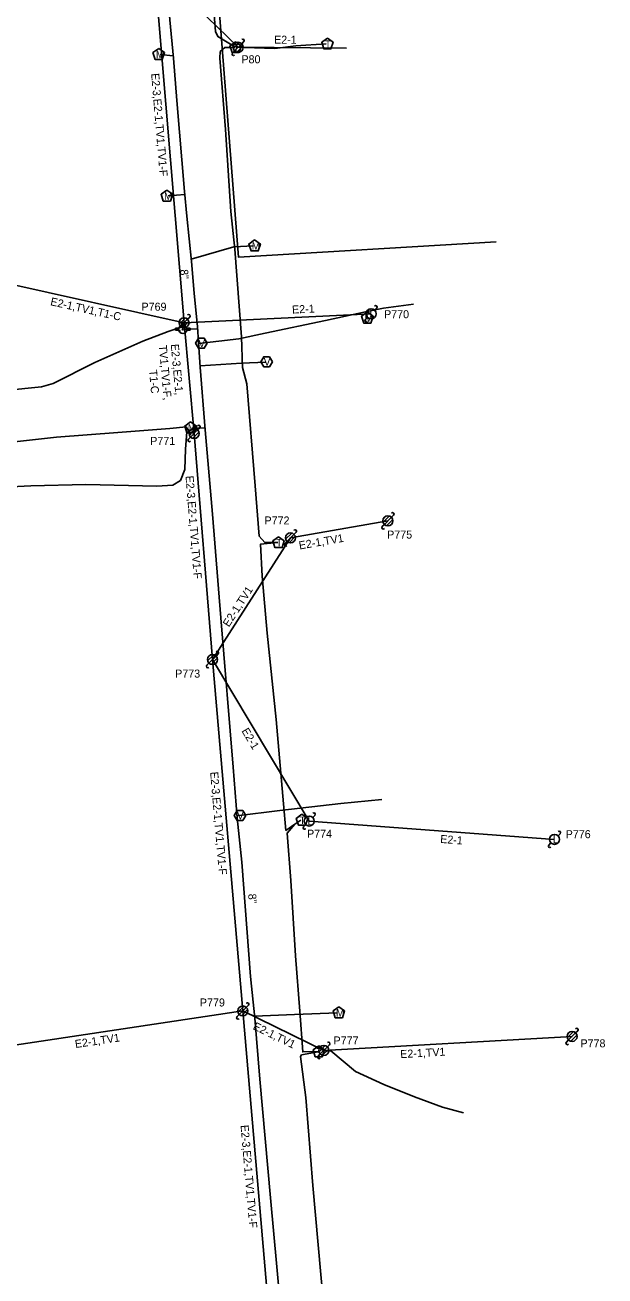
# Model space of a CAD drawing. Extents: x 1614474 to 1865144, y 1098877 to 1212550.
# Drawn here: x 1756233 to 1756523, y 1167576 to 1168201 of the extents above; entities that cross this region are included whole.
import ezdxf

# ---------------------------------------------------------------- set-up
doc = ezdxf.new("R2010")
doc.units = 0
for name, color, linetype in [('RD_EX_SU_Elec', 7, 'Continuous'), ('RD_EX_SU_H2O', 7, 'Continuous'), ('RD_EX_SU_Ovhd', 7, 'Continuous'), ('RD_EX_SU_Pole', 7, 'Continuous'), ('RD_EX_SU_Sewer', 7, 'Continuous'), ('RD_EX_SU_Telecom', 7, 'Continuous'), ('RD_EX_SU_TX_H2O', 7, 'Continuous'), ('RD_EX_SU_TX_Pole', 7, 'Continuous')]:
    doc.layers.add(name, color=color, linetype=linetype)

# ---------------------------------------------------------------- blocks, each defined once
blk = doc.blocks.new('SUE_WM')
at = {"layer": 'RD_EX_SU_H2O'}
blk.add_lwpolyline([(0, 3.05), (-2.9, 0.94), (-1.79, -2.47), (1.79, -2.47), (2.9, 0.94)], close=True, dxfattribs=at)
blk.add_text('M', height=3.75, dxfattribs=at).set_placement((-1.43, -1.88))
blk = doc.blocks.new('SUE_TPP')
at = {"layer": 'RD_EX_SU_Telecom'}
blk.add_lwpolyline([(0, 3), (-2.85, 0.93), (-1.76, -2.43), (1.76, -2.43), (2.85, 0.93)], close=True, dxfattribs=at)
blk.add_text('T', height=3.75, dxfattribs=at).set_placement((-1.25, -1.88))
blk = doc.blocks.new('SUE_WFH')
at = {"layer": 'RD_EX_SU_H2O'}
for p, q in [((-2.01, 0.6), (-3.65, 0.6)), ((-3.65, 0.6), (-3.65, -0.45)), ((-0.48, 3.38), (-0.48, 2.04)), ((0.57, 3.38), (-0.48, 3.38)), ((0.57, 2.02), (0.57, 3.38)), ((3.7, 0.6), (2.01, 0.6)), ((3.7, -0.45), (3.7, 0.6)), ((-3.65, -0.45), (-2.05, -0.45)), ((2.05, -0.45), (3.7, -0.45))]:
    blk.add_line(p, q, dxfattribs=at)
for radius in [2.1, 0.263]:
    blk.add_circle((0, 0), radius, dxfattribs=at)
for start, end in [(163.3387, 192.31502), (74.24552, 103.21276), (347.68498, 16.6613)]:
    blk.add_arc((0, 0), 2.1, start, end, dxfattribs=at)
blk = doc.blocks.new('SUE_WV')
at = {"layer": 'RD_EX_SU_H2O'}
blk.add_lwpolyline([(2.89, 0), (1.44, 2.5), (-1.44, 2.5), (-2.89, 0), (-1.44, -2.5), (1.44, -2.5)], close=True, dxfattribs=at)
blk.add_text('V', height=3.75, dxfattribs=at).set_placement((-1.43, -1.88))
blk = doc.blocks.new('SUE_PP')
at = {"layer": 'RD_EX_SU_Pole'}
for p, q in [((-2.41, -0.65), (0.65, 2.41)), ((-1.77, -1.77), (1.77, 1.77)), ((-0.65, -2.41), (2.41, 0.65)), ((1.77, 1.77), (2.83, 2.83)), ((-2.83, -2.83), (-1.77, -1.77))]:
    blk.add_line(p, q, dxfattribs=at)
blk.add_circle((0, 0), 2.5, dxfattribs=at)
for centre, start, end in [((2.3, 3.36), 315, 135), ((-2.3, -3.36), 135, 315)]:
    blk.add_arc(centre, 0.75, start, end, dxfattribs=at)

msp = doc.modelspace()

# ---------------------------------------------------------------- linework, layer by layer
at = {"layer": 'RD_EX_SU_Elec'}
msp.add_lwpolyline([(1756158.7, 1167983.99), (1756163.59, 1167983.56), (1756187.17, 1167988.03), (1756217.4, 1167991.66), (1756249.02, 1167995.12), (1756279.77, 1167997.42), (1756305.79, 1167999.38), (1756313.88, 1168000.27), (1756316.19, 1167996.26)], dxfattribs=at)
at = {"layer": 'RD_EX_SU_H2O'}
for p, q in [((1756307.47, 1168185.66), (1756300.96, 1168186.31)), ((1756313.25, 1168116.46), (1756304.98, 1168115.68)), ((1756404.41, 1168055.03), (1756404.06, 1168057.9)), ((1756319.41, 1168049.21), (1756313.16, 1168048.96)), ((1756323.32, 1167999.75), (1756316.73, 1167999.65))]:
    msp.add_line(p, q, dxfattribs=at)
for points in [[(1756285.17, 1168453.36), (1756286.98, 1168430.89), (1756288.84, 1168410.54), (1756290.69, 1168387.38), (1756292.59, 1168362.89), (1756293.61, 1168347.16), (1756296.92, 1168313.47), (1756298.02, 1168299), (1756300.93, 1168264.73), (1756302.72, 1168240.2), (1756304.28, 1168222.7), (1756305.65, 1168203.75), (1756307.59, 1168184.55), (1756309.19, 1168163.34), (1756313.11, 1168117.87), (1756314.27, 1168105.58), (1756316.49, 1168082.9), (1756317.85, 1168067.08)], [(1756316.37, 1168084.09), (1756337.79, 1168090.19), (1756347.49, 1168090.77)], [(1756317.85, 1168067.08), (1756319.54, 1168050.19), (1756320.11, 1168042.67), (1756320.97, 1168030.07), (1756323.39, 1167998.84), (1756327.05, 1167956.56), (1756331.25, 1167904.83), (1756337.4, 1167830.13), (1756339.37, 1167804.89), (1756341.64, 1167782.73), (1756346.05, 1167725.54), (1756348.16, 1167704.76), (1756350.69, 1167674.25), (1756356.07, 1167614.92), (1756363.99, 1167527.76)], [(1756320.16, 1168041.86), (1756340.19, 1168044.22), (1756353.43, 1168047.04), (1756383.46, 1168053.37), (1756403.52, 1168057.78), (1756412.53, 1168059.65), (1756427.58, 1168061.53)], [(1756320.92, 1168030.83), (1756341.5, 1168032.11), (1756353.7, 1168032.64)], [(1756339.29, 1167805.94), (1756360.77, 1167808.6), (1756391.2, 1167811.99), (1756411.72, 1167814.03)], [(1756348.06, 1167705.73), (1756368.09, 1167706.65), (1756389.58, 1167707.36)]]:
    msp.add_lwpolyline(points, dxfattribs=at)
at = {"layer": 'RD_EX_SU_Ovhd'}
for p, q in [((1756297.87, 1168230.98), (1756339.88, 1168189.94)), ((1756297.87, 1168230.98), (1756312.84, 1168052.28)), ((1756339.88, 1168189.94), (1756394.05, 1168189.45)), ((1756221.7, 1168072.64), (1756312.84, 1168052.28)), ((1756312.84, 1168052.28), (1756406.3, 1168056.76)), ((1756312.84, 1168052.28), (1756317.86, 1167996.94)), ((1756317.86, 1167996.94), (1756327.05, 1167883.97)), ((1756366, 1167944.76), (1756414.72, 1167953.29)), ((1756327.05, 1167883.97), (1756366, 1167944.76)), ((1756327.05, 1167883.97), (1756342.18, 1167708.36)), ((1756327.05, 1167883.97), (1756375.39, 1167803.26)), ((1756375.39, 1167803.26), (1756497.97, 1167794.1)), ((1756206.43, 1167688.08), (1756342.18, 1167708.36)), ((1756342.18, 1167708.36), (1756356.4, 1167543.03)), ((1756342.18, 1167708.36), (1756382.71, 1167688.62)), ((1756382.71, 1167688.62), (1756506.75, 1167695.61))]:
    msp.add_line(p, q, dxfattribs=at)
at = {"layer": 'RD_EX_SU_Pole'}
for p, q in [((1756337.05, 1168187.11), (1756338.11, 1168188.17)), ((1756337.46, 1168189.29), (1756340.52, 1168192.35)), ((1756338.11, 1168188.17), (1756341.64, 1168191.71)), ((1756339.23, 1168187.53), (1756342.29, 1168190.59)), ((1756341.64, 1168191.71), (1756342.7, 1168192.77)), ((1756408.06, 1168058.53), (1756409.12, 1168059.59)), ((1756403.47, 1168053.93), (1756404.53, 1168054.99)), ((1756411.89, 1167950.46), (1756412.95, 1167951.52)), ((1756412.3, 1167952.64), (1756415.36, 1167955.71)), ((1756412.95, 1167951.52), (1756416.48, 1167955.06)), ((1756414.07, 1167950.88), (1756417.13, 1167953.94)), ((1756416.48, 1167955.06), (1756417.54, 1167956.12)), ((1756363.59, 1167944.11), (1756366.65, 1167947.17)), ((1756364.24, 1167942.99), (1756367.77, 1167946.52)), ((1756365.36, 1167942.34), (1756368.42, 1167945.4)), ((1756367.77, 1167946.52), (1756368.83, 1167947.59)), ((1756363.17, 1167941.93), (1756364.24, 1167942.99)), ((1756324.22, 1167881.14), (1756325.28, 1167882.2)), ((1756324.63, 1167883.32), (1756327.69, 1167886.38)), ((1756325.28, 1167882.2), (1756328.81, 1167885.74)), ((1756326.4, 1167881.56), (1756329.46, 1167884.62)), ((1756328.81, 1167885.74), (1756329.87, 1167886.8)), ((1756372.56, 1167800.43), (1756373.62, 1167801.5)), ((1756377.16, 1167805.03), (1756378.22, 1167806.09)), ((1756499.74, 1167795.87), (1756500.8, 1167796.93)), ((1756495.14, 1167791.27), (1756496.21, 1167792.33))]:
    msp.add_line(p, q, dxfattribs=at)
for centre in [(1756339.88, 1168189.94), (1756406.3, 1168056.76), (1756414.72, 1167953.29), (1756366, 1167944.76), (1756327.05, 1167883.97), (1756375.39, 1167803.26), (1756497.97, 1167794.1)]:
    msp.add_circle(centre, 2.5, dxfattribs=at)
for centre, start, end in [((1756342.17, 1168193.3), 315, 135), ((1756337.58, 1168186.58), 135, 315), ((1756408.59, 1168060.12), 315, 135), ((1756404, 1168053.4), 135, 315), ((1756417.01, 1167956.65), 315, 135), ((1756368.3, 1167948.12), 315, 135), ((1756412.42, 1167949.93), 135, 315), ((1756363.71, 1167941.4), 135, 315), ((1756329.34, 1167887.33), 315, 135), ((1756324.75, 1167880.61), 135, 315), ((1756377.69, 1167806.62), 315, 135), ((1756373.09, 1167799.9), 135, 315), ((1756500.27, 1167797.46), 315, 135), ((1756495.67, 1167790.74), 135, 315)]:
    msp.add_arc(centre, 0.75, start, end, dxfattribs=at)
at = {"layer": 'RD_EX_SU_Sewer'}
msp.add_lwpolyline([(1756311.13, 1168456.78), (1756340.11, 1168085.05), (1756468.76, 1168092.7)], dxfattribs=at)
at = {"layer": 'RD_EX_SU_Telecom'}
for points in [[(1756308.42, 1168448.32), (1756311.91, 1168423.81), (1756311.76, 1168420.79), (1756309.33, 1168416.48), (1756312.58, 1168380.89), (1756316.49, 1168351.19), (1756321.57, 1168300.36), (1756322.32, 1168273.16), (1756326.95, 1168219.13), (1756328.55, 1168197.8), (1756329.78, 1168195.34), (1756338.22, 1168190.16)], [(1756338.16, 1168189.78), (1756333.21, 1168189.81), (1756330.86, 1168187.79), (1756330.68, 1168184.52), (1756333.54, 1168148.9), (1756336.25, 1168107.92), (1756338.14, 1168089.1), (1756341.61, 1168045.19), (1756342.02, 1168029.89), (1756344.16, 1168021.72), (1756348.34, 1167970.86), (1756350.41, 1167945.66), (1756353.23, 1167942.43), (1756359.64, 1167942.51)], [(1756339.2, 1168190.05), (1756342.94, 1168189.85), (1756358.25, 1168189.37), (1756368.67, 1168190.63), (1756383.86, 1168191.61)], [(1756159.04, 1167984.63), (1756166.68, 1167984.37), (1756176.55, 1167987.23), (1756186.47, 1167992.4), (1756190.44, 1167996.92), (1756193.4, 1168006.42), (1756198.16, 1168010.87), (1756216.42, 1168016.99), (1756223.51, 1168018.39), (1756241.64, 1168020.25), (1756247.48, 1168021.99), (1756268.27, 1168032.44), (1756292.3, 1168043.12), (1756304.83, 1168047.91), (1756313.37, 1168050.78), (1756313.03, 1168052.57)], [(1756158.59, 1167985.22), (1756162.2, 1167983.17), (1756168.33, 1167976.76), (1756180.21, 1167969.34), (1756190.12, 1167968.53), (1756236.31, 1167970.8), (1756263.75, 1167971.46), (1756299.2, 1167970.68), (1756307.27, 1167971.19), (1756311.09, 1167973.51), (1756313.18, 1167978.88), (1756313.61, 1167989.06), (1756314.16, 1167997.74), (1756316.41, 1167997.29)], [(1756359.48, 1167942.44), (1756351.11, 1167941.7), (1756351.95, 1167925.63), (1756354.4, 1167897.16), (1756358.92, 1167853.95), (1756362.5, 1167811.93), (1756363.77, 1167798.56), (1756368.25, 1167801.76), (1756371.25, 1167803.66)], [(1756371.22, 1167803.69), (1756368.25, 1167801.64), (1756364.32, 1167797.23), (1756366.22, 1167773.48), (1756368.54, 1167735.91), (1756370.77, 1167708.23), (1756372.16, 1167687.85), (1756379.89, 1167688.13)], [(1756383.1, 1167688.32), (1756386.12, 1167688.46), (1756398.58, 1167678.13), (1756412.62, 1167671.56), (1756428, 1167665.46), (1756441.94, 1167660.34), (1756452.56, 1167657.36)], [(1756379.84, 1167687.97), (1756371.61, 1167686.43), (1756371.04, 1167685.63), (1756373.7, 1167665.14), (1756377.25, 1167621.18), (1756381.27, 1167576.66), (1756385.09, 1167535.47)]]:
    msp.add_lwpolyline(points, dxfattribs=at)

# ---------------------------------------------------------------- block references
at = {"layer": 'RD_EX_SU_H2O'}
for name, p in [('SUE_WM', (1756300.18, 1168186.37)), ('SUE_WM', (1756304.26, 1168115.55)), ('SUE_WM', (1756348.09, 1168090.67)), ('SUE_WM', (1756404.46, 1168054.62)), ('SUE_WFH', (1756312.24, 1168049.01)), ('SUE_WV', (1756321.45, 1168042.03)), ('SUE_WV', (1756354.1, 1168032.8)), ('SUE_WM', (1756316.09, 1167999.71)), ('SUE_WV', (1756340.74, 1167806.05)), ('SUE_WM', (1756390.2, 1167707.41))]:
    msp.add_blockref(name, p, dxfattribs=at)
at = {"layer": 'RD_EX_SU_Pole'}
for p in [(1756312.84, 1168052.28), (1756317.86, 1167996.94), (1756342.18, 1167708.36), (1756506.75, 1167695.61), (1756382.71, 1167688.62)]:
    msp.add_blockref('SUE_PP', p, dxfattribs=at)
at = {"layer": 'RD_EX_SU_Telecom'}
for p in [(1756384.5, 1168191.53), (1756338.61, 1168189.72), (1756360.03, 1167942.36), (1756371.77, 1167803.65), (1756380.17, 1167687.93)]:
    msp.add_blockref('SUE_TPP', p, dxfattribs=at)

# ---------------------------------------------------------------- texts
at = {"layer": 'RD_EX_SU_Ovhd'}
for s, rotation, p in [('E2-1', 359.47922, (1756357.8, 1168191.78)), ('E2-3,E2-1,TV1,TV1-F', 274.78694, (1756296.39, 1168176.83)), ('E2-1,TV1,T1-C', 347.40599, (1756245.77, 1168061.11)), ('E2-1', 2.7473, (1756366.89, 1168056.87)), ('TV1,TV1-F,', 275.18336, (1756300.22, 1168040.97)), ('E2-3,E2-1,', 275.18336, (1756306.2, 1168041.51)), ('T1-C', 275.18336, (1756295.32, 1168028.58)), ('E2-3,E2-1,TV1,TV1-F', 274.64996, (1756313.57, 1167975.68)), ('E2-1,TV1', 9.9369, (1756370.58, 1167938.96)), ('E2-1,TV1', 57.34496, (1756335.26, 1167899.93)), ('E2-1', 300.92124, (1756341.41, 1167848.31)), ('E2-3,E2-1,TV1,TV1-F', 274.92539, (1756325.87, 1167827.73)), ('E2-1', 355.72628, (1756440.74, 1167792.36)), ('E2-1,TV1', 334.02741, (1756346.93, 1167699.37)), ('E2-1,TV1', 8.49892, (1756258.61, 1167689.81)), ('E2-1,TV1', 3.22525, (1756420.98, 1167684.76)), ('E2-3,E2-1,TV1,TV1-F', 274.91654, (1756341.07, 1167651.24))]:
    msp.add_text(s, height=4, rotation=rotation, dxfattribs=at).set_placement(p)
at = {"layer": 'RD_EX_SU_Pole'}
for p in [(1756405.43, 1168054.76), (1756374.53, 1167801.26), (1756497.11, 1167792.1)]:
    msp.add_text('L', height=4, dxfattribs=at).set_placement(p)
at = {"layer": 'RD_EX_SU_TX_H2O'}
for rotation, p in [(274.92643, (1756310.82, 1168078.81)), (274.41179, (1756344.87, 1167766.81))]:
    msp.add_text('8"', height=4, rotation=rotation, dxfattribs=at).set_placement(p)
at = {"layer": 'RD_EX_SU_TX_Pole'}
for s, p in [('P80', (1756341.51, 1168181.96)), ('P769', (1756291.57, 1168058.31)), ('P770', (1756412.79, 1168054.56)), ('P771', (1756295.94, 1167991.23)), ('P772', (1756353.04, 1167951.48)), ('P775', (1756414.33, 1167944.42)), ('P773', (1756308.4, 1167874.96)), ('P774', (1756374.31, 1167794.95)), ('P776', (1756503.56, 1167794.7)), ('P779', (1756320.76, 1167710.59)), ('P777', (1756387.55, 1167691.6)), ('P778', (1756510.94, 1167690.19))]:
    msp.add_text(s, height=4, dxfattribs=at).set_placement(p)

doc.saveas('drawing.dxf')
